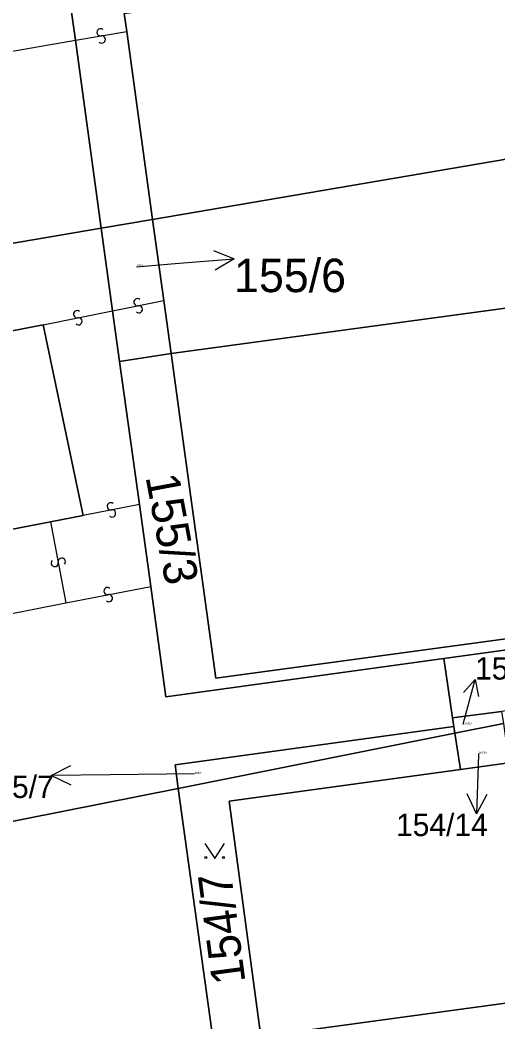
# Model space of a CAD drawing. Extents: x -600309 to -598967, y -1161267 to -1160292.
# Drawn here: x -599224.1 to -599199.9, y -1160714.1 to -1160663.1 of the extents above; entities that cross this region are included whole.
import ezdxf

# ---------------------------------------------------------------- set-up
doc = ezdxf.new("R2010")
doc.units = 0
for name, color, linetype in [('Level 1', 7, 'Continuous'), ('Level 13', 7, 'Continuous'), ('Level 3', 7, 'Continuous'), ('Level 4', 7, 'Continuous'), ('Level 5', 7, 'Continuous'), ('Level 57', 7, 'Continuous'), ('Level 60', 7, 'Continuous')]:
    doc.layers.add(name, color=color, linetype=linetype)

msp = doc.modelspace()

# ---------------------------------------------------------------- linework, layer by layer
at = {"layer": 'Level 1'}
for points in [[(-599221.33, -1160664.16), (-599222.03, -1160659.14)], [(-599218.72, -1160663.71), (-599218.85, -1160662.8), (-599207.24, -1160661.23)], [(-599218.72, -1160663.71), (-599217.41, -1160673.27)], [(-599220.02, -1160673.72), (-599221.33, -1160664.16)], [(-599162.08, -1160664.59), (-599195.77, -1160669.58), (-599217.41, -1160673.27)], [(-599216.47, -1160680.09), (-599160.99, -1160672.57)], [(-599217.41, -1160673.27), (-599220.02, -1160673.72)], [(-599217.41, -1160673.27), (-599216.84, -1160677.4)], [(-599220.02, -1160673.72), (-599247.13, -1160678.34)], [(-599219.44, -1160677.92), (-599220.02, -1160673.72)], [(-599216.84, -1160677.4), (-599216.47, -1160680.09)], [(-599219.08, -1160680.5), (-599219.44, -1160677.92)], [(-599246.31, -1160683.15), (-599222.97, -1160678.63)], [(-599222.97, -1160678.63), (-599220.93, -1160688.32)], [(-599219.08, -1160680.5), (-599216.47, -1160680.09)], [(-599216.47, -1160680.09), (-599215.48, -1160687.27), (-599214.91, -1160691.42), (-599214.2, -1160696.59), (-599168.85, -1160690.44)], [(-599218.08, -1160687.77), (-599219.08, -1160680.5)], [(-599217.5, -1160691.93), (-599218.08, -1160687.77)], [(-599220.93, -1160688.32), (-599222.59, -1160688.65)], [(-599222.59, -1160688.65), (-599237.67, -1160691.56)], [(-599168.75, -1160690.93), (-599202.61, -1160695.59)], [(-599217.5, -1160691.93), (-599216.73, -1160697.54), (-599202.61, -1160695.59)], [(-599202.61, -1160695.59), (-599202.16, -1160698.62)], [(-599202.16, -1160698.62), (-599199.67, -1160698.29)], [(-599202.16, -1160698.62), (-599202.09, -1160699.05)], [(-599216.1, -1160702.2), (-599216.26, -1160701.01), (-599202.09, -1160699.05)], [(-599202.09, -1160699.05), (-599202.04, -1160699.4)], [(-599202.04, -1160699.4), (-599199.58, -1160698.91)], [(-599216.1, -1160702.2), (-599202.04, -1160699.4)], [(-599202.04, -1160699.4), (-599201.76, -1160701.24)], [(-599211.9, -1160714.81), (-599213.52, -1160702.85), (-599201.76, -1160701.24)], [(-599201.76, -1160701.24), (-599199.31, -1160700.9)], [(-599216.1, -1160702.2), (-599233.89, -1160705.74), (-599234.03, -1160705.08)], [(-599216.1, -1160702.2), (-599213.89, -1160718.19), (-599211.49, -1160717.86)], [(-599211.9, -1160714.81), (-599182.2, -1160710.76)]]:
    msp.add_lwpolyline(points, dxfattribs=at)
at = {"layer": 'Level 13'}
for centre, start, end in [((-599220.05, -1160663.758), 47.1551, 279.2531), ((-599219.99, -1160664.122), 226.9407, 99.5307), ((-599218.175, -1160677.479), 48.6827, 280.7807), ((-599218.105, -1160677.841), 228.4682, 101.0582), ((-599221.245, -1160678.089), 48.7451, 280.8431), ((-599221.174, -1160678.451), 228.5306, 101.1206), ((-599219.534, -1160687.859), 48.0811, 280.6711), ((-599219.467, -1160688.221), 228.2955, 100.3935), ((-599222.381, -1160690.743), 137.8787, 10.4687), ((-599222.018, -1160690.677), 318.0931, 190.1911), ((-599219.694, -1160692.169), 48.4012, 280.4992), ((-599219.626, -1160692.531), 228.1867, 100.7767)]:
    msp.add_arc(centre, 0.184, start, end, dxfattribs=at)
at = {"layer": 'Level 3'}
for points in [[(-599221.33, -1160664.16), (-599218.72, -1160663.71)], [(-599243.12, -1160667.96), (-599221.33, -1160664.16)], [(-599219.44, -1160677.92), (-599216.84, -1160677.4)], [(-599222.97, -1160678.63), (-599219.44, -1160677.92)], [(-599218.08, -1160687.77), (-599220.93, -1160688.32)], [(-599222.59, -1160688.65), (-599221.81, -1160692.77)], [(-599221.81, -1160692.77), (-599217.5, -1160691.93)], [(-599235.87, -1160695.54), (-599221.81, -1160692.77)]]:
    msp.add_lwpolyline(points, dxfattribs=at)
at = {"layer": 'Level 5'}
msp.add_lwpolyline([(-599214.751, -1160705.01), (-599214.25, -1160705.76), (-599213.75, -1160705.01)], dxfattribs=at)
for centre in [(-599214.7, -1160705.71), (-599213.801, -1160705.71)]:
    msp.add_circle(centre, 0.05, dxfattribs=at)
at = {"layer": 'Level 57'}
for p, q in [((-599216.255, -1160675.517), (-599213.265, -1160675.27)), ((-599218.22, -1160675.68), (-599216.255, -1160675.517)), ((-599201.62, -1160698.94), (-599201.02, -1160696.67)), ((-599200.852, -1160700.492), (-599200.95, -1160703.49)), ((-599200.85, -1160700.43), (-599200.852, -1160700.492)), ((-599219.554, -1160701.517), (-599222.554, -1160701.55)), ((-599215.27, -1160701.47), (-599219.554, -1160701.517))]:
    msp.add_line(p, q, dxfattribs=at)
for points in [[(-599214.303, -1160674.854), (-599213.265, -1160675.27), (-599214.221, -1160675.85)], [(-599201.598, -1160697.327), (-599201.02, -1160696.67), (-599200.842, -1160697.527)], [(-599221.548, -1160702.039), (-599222.554, -1160701.55), (-599221.559, -1160701.039)], [(-599200.418, -1160702.507), (-599200.95, -1160703.49), (-599201.417, -1160702.475)]]:
    msp.add_lwpolyline(points, dxfattribs=at)
at = {"layer": 'Level 60'}
for points in [[(-599166.02, -1160636.29), (-599175.93, -1160637.7), (-599175.65, -1160639.81), (-599198.49, -1160642.98), (-599224.13, -1160646.54), (-599223.81, -1160649.33), (-599223.44, -1160652.48), (-599222.9, -1160656.99), (-599222.33, -1160656.92), (-599222.03, -1160659.14), (-599221.33, -1160664.16), (-599220.02, -1160673.72), (-599247.13, -1160678.34), (-599248.77, -1160668.96), (-599249.2, -1160666.65), (-599253.36, -1160667.06), (-599253.91, -1160662.3), (-599254.33, -1160658.54), (-599255.43, -1160647.94), (-599254.31, -1160647.8), (-599255.28, -1160639.65), (-599247.11, -1160638.51), (-599237.58, -1160637.19)], [(-599247.13, -1160678.34), (-599220.02, -1160673.72), (-599219.44, -1160677.92), (-599219.08, -1160680.5), (-599218.08, -1160687.77), (-599217.5, -1160691.93), (-599216.73, -1160697.54), (-599202.61, -1160695.59), (-599202.16, -1160698.62), (-599202.09, -1160699.05), (-599216.26, -1160701.01), (-599216.1, -1160702.2), (-599233.89, -1160705.74)], [(-599237.67, -1160691.56), (-599222.59, -1160688.65), (-599220.93, -1160688.32), (-599222.97, -1160678.63), (-599246.31, -1160683.15)], [(-599233.89, -1160705.74), (-599216.1, -1160702.2), (-599213.89, -1160718.19), (-599211.49, -1160717.86), (-599211.03, -1160721.07), (-599186.66, -1160717.69), (-599188.03, -1160719.54), (-599186.49, -1160731.78), (-599199.93, -1160734.74), (-599199.99, -1160734.46), (-599199.12, -1160734.25), (-599199.89, -1160731.02), (-599200.74, -1160731.22), (-599202.12, -1160725.18), (-599206.47, -1160726.19), (-599206.57, -1160725.69), (-599201.27, -1160724.44), (-599202.02, -1160721.23), (-599207.33, -1160722.48), (-599212.68, -1160723.74), (-599211.91, -1160727), (-599211.81, -1160727.43), (-599221.86, -1160729.77), (-599225.29, -1160730.52)]]:
    msp.add_lwpolyline(points, dxfattribs=at)
for points in [[(-599208.72, -1160655.12), (-599208.79, -1160654.62), (-599208.24, -1160654.55), (-599207.24, -1160661.23), (-599218.85, -1160662.8), (-599218.72, -1160663.71), (-599217.41, -1160673.27), (-599220.02, -1160673.72), (-599221.33, -1160664.16), (-599222.03, -1160659.14), (-599222.33, -1160656.92)], [(-599162.08, -1160664.59), (-599195.77, -1160669.58), (-599217.41, -1160673.27), (-599218.72, -1160663.71), (-599218.85, -1160662.8), (-599207.24, -1160661.23), (-599175.21, -1160656.89), (-599173.58, -1160656.66), (-599168.05, -1160655.92), (-599163.36, -1160655.28)], [(-599195.77, -1160669.58), (-599162.08, -1160664.59), (-599160.99, -1160672.57), (-599216.47, -1160680.09), (-599216.84, -1160677.4), (-599217.41, -1160673.27)], [(-599215.48, -1160687.27), (-599216.47, -1160680.09), (-599160.99, -1160672.57), (-599160.62, -1160675.32), (-599166.62, -1160676.39), (-599171.56, -1160677.5), (-599170.43, -1160682.72), (-599170.15, -1160683.92), (-599167.61, -1160684.01), (-599159.41, -1160684.15), (-599158.86, -1160684.16), (-599158.88, -1160685), (-599158.93, -1160687.71), (-599158.74, -1160689.07), (-599158.95, -1160689.1), (-599167.59, -1160690.27), (-599168.85, -1160690.44), (-599214.2, -1160696.59), (-599214.91, -1160691.42)], [(-599219.44, -1160677.92), (-599220.02, -1160673.72), (-599217.41, -1160673.27), (-599216.84, -1160677.4), (-599216.47, -1160680.09), (-599219.08, -1160680.5)], [(-599242.54, -1160693.61), (-599250.07, -1160695.01), (-599250.29, -1160694.07), (-599264.29, -1160696.81), (-599265.82, -1160688.93), (-599263.31, -1160688.67), (-599263.54, -1160686.57), (-599246.7, -1160683.23), (-599246.31, -1160683.15), (-599222.97, -1160678.63), (-599220.93, -1160688.32), (-599222.59, -1160688.65), (-599237.67, -1160691.56), (-599240.36, -1160692.13), (-599240.19, -1160693.14)], [(-599216.73, -1160697.54), (-599217.5, -1160691.93), (-599218.08, -1160687.77), (-599219.08, -1160680.5), (-599216.47, -1160680.09), (-599215.48, -1160687.27), (-599214.91, -1160691.42), (-599214.2, -1160696.59), (-599168.85, -1160690.44), (-599168.75, -1160690.93), (-599202.61, -1160695.59)], [(-599189.52, -1160696.9), (-599199.67, -1160698.29), (-599202.16, -1160698.62), (-599202.61, -1160695.59), (-599168.75, -1160690.93), (-599168.39, -1160692.7)], [(-599182.11, -1160711.56), (-599174.64, -1160709.73), (-599156.11, -1160707.2), (-599154.64, -1160705.58), (-599156.35, -1160692.75), (-599156.36, -1160692.65), (-599156.16, -1160692.73), (-599155.8, -1160692.87), (-599155.18, -1160693.13), (-599154.26, -1160694.29), (-599153.97, -1160695.33), (-599152.89, -1160703.46), (-599152.84, -1160704.47), (-599153.04, -1160705.47), (-599153.86, -1160706.99), (-599155.52, -1160708.49), (-599157.24, -1160709.21), (-599211.64, -1160716.77), (-599211.9, -1160714.81), (-599182.2, -1160710.76)], [(-599202.04, -1160699.4), (-599202.09, -1160699.05), (-599202.16, -1160698.62), (-599199.67, -1160698.29), (-599199.58, -1160698.91)], [(-599216.1, -1160702.2), (-599216.26, -1160701.01), (-599202.09, -1160699.05), (-599202.04, -1160699.4)], [(-599196.08, -1160701.12), (-599195.89, -1160701.13), (-599192.14, -1160700.41), (-599188.19, -1160699.58), (-599185.14, -1160698.97), (-599184.16, -1160698.84), (-599182.73, -1160705.92), (-599182.2, -1160710.76), (-599211.9, -1160714.81), (-599213.52, -1160702.85), (-599201.76, -1160701.24), (-599199.31, -1160700.9), (-599196.21, -1160700.48)], [(-599199.58, -1160698.91), (-599199.31, -1160700.9), (-599201.76, -1160701.24), (-599202.04, -1160699.4)], [(-599211.9, -1160714.81), (-599211.64, -1160716.77), (-599211.49, -1160717.86), (-599213.89, -1160718.19), (-599216.1, -1160702.2), (-599202.04, -1160699.4), (-599201.76, -1160701.24), (-599213.52, -1160702.85)]]:
    msp.add_lwpolyline(points, close=True, dxfattribs=at)

# ---------------------------------------------------------------- texts
at = {"layer": 'Level 4'}
for s, p in [('155/6', (-599218.22, -1160675.68)), ('155/23', (-599201.62, -1160698.94)), ('154/14', (-599200.85, -1160700.43)), ('155/7', (-599215.27, -1160701.47))]:
    msp.add_text(s, height=0.1, dxfattribs=at).set_placement(p)
for s, rotation, p in [('155/3', 280.6118, (-599217.771, -1160686.358)), ('154/7', 97.5523, (-599212.681, -1160712.044))]:
    msp.add_text(s, height=1.7, rotation=rotation, dxfattribs=at).set_placement(p)
at = {"layer": 'Level 57'}
for s, height, p in [('155/6', 1.7, (-599213.265, -1160676.97)), ('155/23', 1.14, (-599201.02, -1160696.67)), ('155/7', 1.14, (-599226.246, -1160702.69)), ('154/14', 1.14, (-599205.036, -1160704.63))]:
    msp.add_text(s, height=height, dxfattribs=at).set_placement(p)

doc.saveas('drawing.dxf')
